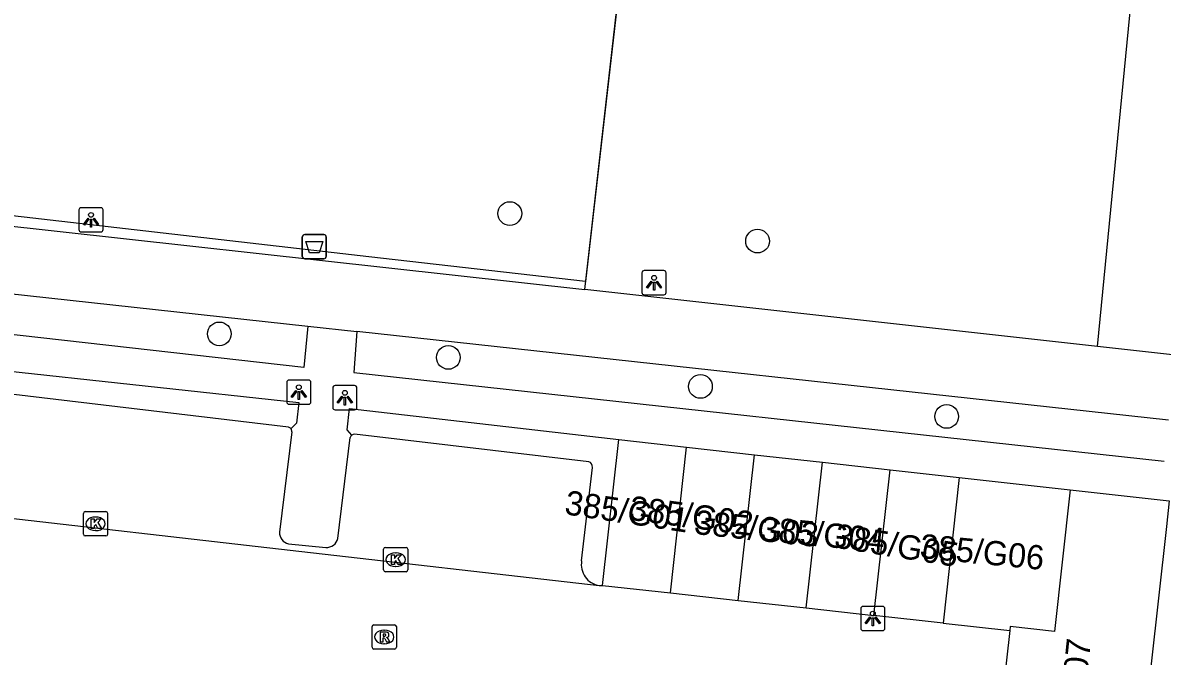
# Model space of a CAD drawing. Extents: x 162026 to 163499, y 387297 to 388169.
# Drawn here: x 162130.69 to 162177.68, y 387827.91 to 387854.05 of the extents above; entities that cross this region are included whole.
import ezdxf

# ---------------------------------------------------------------- set-up
doc = ezdxf.new("R2010")
doc.units = 0
for name, color, linetype in [('IMGEO_Afvalbak', 7, 'Continuous'), ('IMGEO_Boom', 7, 'Continuous'), ('IMGEO_Fietspad_gesloten', 7, 'Continuous'), ('IMGEO_Groenvoorziening', 7, 'Continuous'), ('IMGEO_Hek', 7, 'Continuous'), ('IMGEO_Kolk', 7, 'Continuous'), ('IMGEO_Lichtpunt', 7, 'Continuous'), ('IMGEO_Loofbos', 7, 'Continuous'), ('IMGEO_Pand', 7, 'Continuous'), ('IMGEO_Pand_nummerreeks', 7, 'Continuous'), ('IMGEO_Parkeervlak_open', 7, 'Continuous'), ('IMGEO_Rijbaan_lokaal_open', 7, 'Continuous'), ('IMGEO_Rioolput', 7, 'Continuous'), ('IMGEO_Voetpad_open', 7, 'Continuous')]:
    doc.layers.add(name, color=color, linetype=linetype)

msp = doc.modelspace()

# ---------------------------------------------------------------- linework, layer by layer
at = {"layer": 'IMGEO_Afvalbak'}
for p, q in [((162142.22, 387844.41), (162142.22, 387845.21)), ((162142.22, 387845.21), (162142.22, 387844.41)), ((162142.32, 387845.31), (162143.11, 387845.31)), ((162143.11, 387845.31), (162142.32, 387845.31)), ((162143.21, 387845.21), (162143.21, 387844.41)), ((162143.21, 387844.41), (162143.21, 387845.21)), ((162143.11, 387844.31), (162142.32, 387844.31)), ((162142.32, 387844.31), (162143.11, 387844.31))]:
    msp.add_line(p, q, dxfattribs=at)
msp.add_lwpolyline([(162142.363, 387845.024), (162143.067, 387845.024), (162142.918, 387844.554), (162142.512, 387844.554), (162142.363, 387845.024)], dxfattribs=at)
for centre, start, end in [((162142.32, 387845.21), 90, 180), ((162142.32, 387845.21), 90, 180), ((162143.11, 387845.21), 0, 90), ((162143.11, 387845.21), 360, 90), ((162142.32, 387844.41), 180, 270), ((162142.32, 387844.41), 180, 270), ((162143.11, 387844.41), 270, 0), ((162143.11, 387844.41), 270, 0)]:
    msp.add_arc(centre, 0.1, start, end, dxfattribs=at)
at = {"layer": 'IMGEO_Boom'}
for centre in [(162150.777, 387846.176), (162160.995, 387845.04), (162138.798, 387841.21), (162148.243, 387840.242), (162158.638, 387839.043), (162168.793, 387837.806)]:
    msp.add_circle(centre, 0.489, dxfattribs=at)
at = {"layer": 'IMGEO_Fietspad_gesloten'}
for points in [[(162124.015, 387846.348), (162153.864, 387843.037)], [(162123.707, 387843.579), (162142.441, 387841.533)], [(162175.011, 387840.691), (162153.864, 387843.037)], [(162142.441, 387841.533), (162144.47, 387841.312)], [(162177.938, 387837.659), (162144.47, 387841.312)], [(162179.708, 387840.17), (162175.011, 387840.691)]]:
    msp.add_lwpolyline(points, dxfattribs=at)
at = {"layer": 'IMGEO_Groenvoorziening'}
msp.add_lwpolyline([(162153.864, 387843.037), (162155.543, 387857.784), (162125.681, 387861.129)], dxfattribs=at)
at = {"layer": 'IMGEO_Hek'}
msp.add_lwpolyline([(162125.681, 387861.129), (162155.543, 387857.784), (162153.902, 387843.37), (162144.961, 387844.395), (162141.98, 387844.737), (162124.046, 387846.793)], dxfattribs=at)
at = {"layer": 'IMGEO_Kolk'}
for p, q in [((162133.192, 387832.952), (162133.192, 387833.804)), ((162133.267, 387833.878), (162134.119, 387833.878)), ((162134.193, 387833.804), (162134.193, 387832.952)), ((162133.68, 387833.658), (162133.705, 387833.658)), ((162134.119, 387832.878), (162133.267, 387832.878)), ((162133.703, 387833.098), (162133.678, 387833.098)), ((162145.646, 387832.401), (162146.498, 387832.401)), ((162145.571, 387831.475), (162145.571, 387832.327)), ((162146.059, 387832.181), (162146.084, 387832.181)), ((162146.572, 387832.327), (162146.572, 387831.475)), ((162146.082, 387831.621), (162146.057, 387831.621)), ((162146.498, 387831.401), (162145.646, 387831.401))]:
    msp.add_line(p, q, dxfattribs=at)
for points in [[(162133.192, 387832.952), (162133.192, 387833.804)], [(162133.267, 387833.878), (162134.119, 387833.878)], [(162134.193, 387833.804), (162134.193, 387832.952)], [(162133.513, 387833.578), (162133.636, 387833.578), (162133.636, 387833.427), (162133.766, 387833.578), (162133.93, 387833.578), (162133.784, 387833.427), (162133.937, 387833.178), (162133.785, 387833.178), (162133.7, 387833.342), (162133.636, 387833.275), (162133.636, 387833.178), (162133.513, 387833.178), (162133.513, 387833.578)], [(162134.119, 387832.878), (162133.267, 387832.878)], [(162145.646, 387832.401), (162146.498, 387832.401)], [(162145.571, 387831.475), (162145.571, 387832.327)], [(162145.892, 387832.101), (162146.015, 387832.101), (162146.015, 387831.95), (162146.145, 387832.101), (162146.309, 387832.101), (162146.163, 387831.95), (162146.316, 387831.701), (162146.164, 387831.701), (162146.079, 387831.865), (162146.015, 387831.798), (162146.015, 387831.701), (162145.892, 387831.701), (162145.892, 387832.101)], [(162146.572, 387832.327), (162146.572, 387831.475)], [(162146.498, 387831.401), (162145.646, 387831.401)]]:
    msp.add_lwpolyline(points, dxfattribs=at)
for centre, start, end in [((162133.269, 387833.802), 91.552, 178.448), ((162133.269, 387833.802), 91.552, 178.448), ((162134.117, 387833.802), 1.552, 88.448), ((162134.117, 387833.802), 1.552, 88.448), ((162133.269, 387832.954), 181.552, 268.448), ((162133.269, 387832.954), 181.552, 268.448), ((162134.117, 387832.954), 271.552, 358.448), ((162134.117, 387832.954), 271.552, 358.448), ((162145.648, 387832.325), 91.552, 178.448), ((162145.648, 387832.325), 91.552, 178.448), ((162146.496, 387832.325), 1.552, 88.448), ((162146.496, 387832.325), 1.552, 88.448), ((162145.648, 387831.477), 181.552, 268.448), ((162145.648, 387831.477), 181.552, 268.448), ((162146.496, 387831.477), 271.552, 358.448), ((162146.496, 387831.477), 271.552, 358.448)]:
    msp.add_arc(centre, 0.0765, start, end, dxfattribs=at)
for centre, major_axis, ratio, start_param, end_param in [((162133.679, 387833.378), (-0.387, 0.002), 0.722429, 4.712389, 7.853982), ((162133.704, 387833.378), (-0.39, 0.002), 0.717154, 1.570796, 4.712389), ((162146.058, 387831.901), (-0.387, 0.002), 0.722429, 4.712389, 7.853982), ((162146.083, 387831.901), (-0.39, 0.002), 0.717154, 1.570796, 4.712389)]:
    msp.add_ellipse(centre, major_axis=major_axis, ratio=ratio, start_param=start_param, end_param=end_param, dxfattribs=at)
at = {"layer": 'IMGEO_Lichtpunt'}
for p, q in [((162133.009, 387846.322), (162133.009, 387845.515)), ((162133.009, 387846.322), (162133.009, 387845.515)), ((162133.911, 387846.417), (162133.103, 387846.417)), ((162133.911, 387846.417), (162133.103, 387846.417)), ((162134.005, 387845.515), (162134.005, 387846.322)), ((162134.005, 387845.515), (162134.005, 387846.322)), ((162133.103, 387845.421), (162133.911, 387845.421)), ((162133.103, 387845.421), (162133.911, 387845.421)), ((162156.228, 387843.725), (162156.228, 387842.918)), ((162156.228, 387843.725), (162156.228, 387842.918)), ((162157.13, 387843.82), (162156.322, 387843.82)), ((162157.13, 387843.82), (162156.322, 387843.82)), ((162157.224, 387842.918), (162157.224, 387843.725)), ((162157.224, 387842.918), (162157.224, 387843.725)), ((162156.322, 387842.824), (162157.13, 387842.824)), ((162156.322, 387842.824), (162157.13, 387842.824)), ((162141.578, 387839.213), (162141.578, 387838.406)), ((162141.578, 387839.213), (162141.578, 387838.406)), ((162142.48, 387839.308), (162141.672, 387839.308)), ((162142.48, 387839.308), (162141.672, 387839.308)), ((162142.574, 387838.406), (162142.574, 387839.213)), ((162142.574, 387838.406), (162142.574, 387839.213)), ((162143.477, 387838.983), (162143.477, 387838.176)), ((162143.477, 387838.983), (162143.477, 387838.176)), ((162144.379, 387839.078), (162143.571, 387839.078)), ((162144.379, 387839.078), (162143.571, 387839.078)), ((162144.473, 387838.176), (162144.473, 387838.983)), ((162144.473, 387838.176), (162144.473, 387838.983)), ((162141.672, 387838.312), (162142.48, 387838.312)), ((162141.672, 387838.312), (162142.48, 387838.312)), ((162143.571, 387838.082), (162144.379, 387838.082)), ((162143.571, 387838.082), (162144.379, 387838.082)), ((162165.25, 387829.876), (162165.25, 387829.069)), ((162165.25, 387829.876), (162165.25, 387829.069)), ((162166.152, 387829.971), (162165.344, 387829.971)), ((162166.152, 387829.971), (162165.344, 387829.971)), ((162166.246, 387829.069), (162166.246, 387829.876)), ((162166.246, 387829.069), (162166.246, 387829.876)), ((162165.344, 387828.975), (162166.152, 387828.975)), ((162165.344, 387828.975), (162166.152, 387828.975))]:
    msp.add_line(p, q, dxfattribs=at)
for points in [[(162133.383, 387845.986), (162133.422, 387845.958), (162133.234, 387845.696), (162133.196, 387845.723), (162133.383, 387845.986)], [(162133.485, 387845.938), (162133.532, 387845.938), (162133.532, 387845.616), (162133.485, 387845.616), (162133.485, 387845.938)], [(162133.595, 387845.958), (162133.633, 387845.985), (162133.82, 387845.723), (162133.781, 387845.695), (162133.595, 387845.958)], [(162156.602, 387843.389), (162156.641, 387843.361), (162156.453, 387843.099), (162156.415, 387843.126), (162156.602, 387843.389)], [(162156.704, 387843.341), (162156.751, 387843.341), (162156.751, 387843.019), (162156.704, 387843.019), (162156.704, 387843.341)], [(162156.814, 387843.361), (162156.852, 387843.388), (162157.039, 387843.126), (162157, 387843.098), (162156.814, 387843.361)], [(162141.952, 387838.877), (162141.991, 387838.849), (162141.803, 387838.587), (162141.765, 387838.614), (162141.952, 387838.877)], [(162142.054, 387838.829), (162142.101, 387838.829), (162142.101, 387838.507), (162142.054, 387838.507), (162142.054, 387838.829)], [(162142.164, 387838.849), (162142.202, 387838.876), (162142.389, 387838.614), (162142.35, 387838.586), (162142.164, 387838.849)], [(162143.851, 387838.647), (162143.89, 387838.619), (162143.702, 387838.357), (162143.664, 387838.384), (162143.851, 387838.647)], [(162143.953, 387838.599), (162144, 387838.599), (162144, 387838.277), (162143.953, 387838.277), (162143.953, 387838.599)], [(162144.063, 387838.619), (162144.101, 387838.646), (162144.288, 387838.384), (162144.249, 387838.356), (162144.063, 387838.619)], [(162165.624, 387829.54), (162165.663, 387829.512), (162165.475, 387829.25), (162165.437, 387829.277), (162165.624, 387829.54)], [(162165.726, 387829.492), (162165.773, 387829.492), (162165.773, 387829.17), (162165.726, 387829.17), (162165.726, 387829.492)], [(162165.836, 387829.512), (162165.874, 387829.539), (162166.061, 387829.277), (162166.022, 387829.249), (162165.836, 387829.512)]]:
    msp.add_lwpolyline(points, dxfattribs=at)
for centre in [(162133.508, 387846.12), (162156.727, 387843.523), (162142.077, 387839.011), (162143.976, 387838.781), (162165.749, 387829.674)]:
    msp.add_circle(centre, 0.0994, dxfattribs=at)
for centre, start, end in [((162133.103, 387846.322), 90, 180), ((162133.103, 387846.322), 90, 180), ((162133.911, 387846.322), 0, 90), ((162133.911, 387846.322), 0, 90), ((162133.103, 387845.515), 180, 270), ((162133.103, 387845.515), 180, 270), ((162133.911, 387845.515), 270, 0), ((162133.911, 387845.515), 270, 360), ((162156.322, 387843.725), 90, 180), ((162156.322, 387843.725), 90, 180), ((162157.13, 387843.725), 0, 90), ((162157.13, 387843.725), 0, 90), ((162156.322, 387842.918), 180, 270), ((162156.322, 387842.918), 180, 270), ((162157.13, 387842.918), 270, 0), ((162157.13, 387842.918), 270, 360), ((162141.672, 387839.213), 90, 180), ((162141.672, 387839.213), 90, 180), ((162142.48, 387839.213), 0, 90), ((162142.48, 387839.213), 0, 90), ((162143.571, 387838.983), 90, 180), ((162143.571, 387838.983), 90, 180), ((162144.379, 387838.983), 0, 90), ((162144.379, 387838.983), 0, 90), ((162141.672, 387838.406), 180, 270), ((162141.672, 387838.406), 180, 270), ((162142.48, 387838.406), 270, 0), ((162142.48, 387838.406), 270, 360), ((162143.571, 387838.176), 180, 270), ((162143.571, 387838.176), 180, 270), ((162144.379, 387838.176), 270, 0), ((162144.379, 387838.176), 270, 360), ((162165.344, 387829.876), 90, 180), ((162165.344, 387829.876), 90, 180), ((162166.152, 387829.876), 0, 90), ((162166.152, 387829.876), 0, 90), ((162165.344, 387829.069), 180, 270), ((162165.344, 387829.069), 180, 270), ((162166.152, 387829.069), 270, 0), ((162166.152, 387829.069), 270, 360)]:
    msp.add_arc(centre, 0.0946, start, end, dxfattribs=at)
at = {"layer": 'IMGEO_Loofbos'}
msp.add_lwpolyline([(162175.011, 387840.691), (162177.571, 387866.907), (162177.598, 387868.402), (162177.312, 387869.89), (162176.723, 387871.285), (162175.856, 387872.528), (162167.785, 387879.745), (162165.386, 387881.891)], dxfattribs=at)
at = {"layer": 'IMGEO_Pand'}
for points in [[(162154.604, 387830.837), (162155.272, 387836.851)], [(162155.272, 387836.851), (162158.07, 387836.54)], [(162157.402, 387830.526), (162158.07, 387836.54)], [(162158.07, 387836.54), (162160.868, 387836.229)], [(162160.2, 387830.215), (162160.868, 387836.229)], [(162160.868, 387836.229), (162163.666, 387835.918)], [(162162.997, 387829.904), (162163.666, 387835.918)], [(162163.666, 387835.918), (162166.464, 387835.607)], [(162165.795, 387829.593), (162166.464, 387835.607)], [(162166.464, 387835.607), (162169.313, 387835.29)], [(162169.313, 387835.29), (162168.645, 387829.276)], [(162169.313, 387835.29), (162173.885, 387834.782)], [(162173.885, 387834.782), (162173.236, 387828.935), (162171.409, 387829.139), (162171.391, 387828.971)], [(162173.885, 387834.782), (162177.973, 387834.328)], [(162177.973, 387834.328), (162177.854, 387833.262), (162176.897, 387824.645)], [(162154.604, 387830.837), (162157.402, 387830.526)], [(162157.402, 387830.526), (162160.2, 387830.215)], [(162160.2, 387830.215), (162162.997, 387829.904)], [(162162.997, 387829.904), (162165.795, 387829.593)], [(162168.645, 387829.276), (162165.795, 387829.593)], [(162168.645, 387829.276), (162171.391, 387828.971)], [(162171.391, 387828.971), (162170.983, 387825.303)]]:
    msp.add_lwpolyline(points, dxfattribs=at)
at = {"layer": 'IMGEO_Parkeervlak_open'}
for points in [[(162141.646, 387837.364), (162129.498, 387838.809)], [(162154.033, 387835.938), (162144.372, 387837.077)], [(162153.739, 387831.847), (162154.185, 387835.704)]]:
    msp.add_lwpolyline(points, dxfattribs=at)
for centre, radius, start, end in [((162141.609, 387837.191), 0.177, 35.6723, 77.9418), ((162144.375, 387836.898), 0.179, 90.9975, 127.4863), ((162153.968, 387835.73), 0.218, 353.2879, 72.7254), ((162154.596, 387831.691), 0.871, 169.6626, 261.0817)]:
    msp.add_arc(centre, radius, start, end, dxfattribs=at)
at = {"layer": 'IMGEO_Rijbaan_lokaal_open'}
for points in [[(162128.746, 387833.776), (162141.717, 387832.294), (162154.461, 387830.83)], [(162154.461, 387830.83), (162154.604, 387830.837)]]:
    msp.add_lwpolyline(points, dxfattribs=at)
at = {"layer": 'IMGEO_Rioolput'}
for p, q in [((162145.098, 387828.283), (162145.098, 387829.135)), ((162145.173, 387829.209), (162146.025, 387829.209)), ((162146.099, 387829.135), (162146.099, 387828.283)), ((162145.586, 387828.989), (162145.611, 387828.989)), ((162146.025, 387828.209), (162145.173, 387828.209)), ((162145.609, 387828.429), (162145.584, 387828.429))]:
    msp.add_line(p, q, dxfattribs=at)
for points in [[(162145.098, 387828.283), (162145.098, 387829.135)], [(162145.173, 387829.209), (162146.025, 387829.209)], [(162146.099, 387829.135), (162146.099, 387828.283)], [(162145.687, 387828.907), (162145.435, 387828.909), (162145.435, 387828.509)], [(162145.435, 387828.509), (162145.559, 387828.509), (162145.559, 387828.671), (162145.57, 387828.671)], [(162145.613, 387828.828), (162145.559, 387828.828), (162145.559, 387828.747)], [(162145.559, 387828.747), (162145.611, 387828.747)], [(162145.617, 387828.642), (162145.688, 387828.509), (162145.828, 387828.509), (162145.763, 387828.635)], [(162146.025, 387828.209), (162145.173, 387828.209)]]:
    msp.add_lwpolyline(points, dxfattribs=at)
for centre, radius, start, end in [((162145.175, 387829.133), 0.0765, 91.552, 178.448), ((162145.175, 387829.133), 0.0765, 91.552, 178.448), ((162146.023, 387829.133), 0.0765, 1.552, 88.448), ((162146.023, 387829.133), 0.0765, 1.552, 88.448), ((162145.569, 387828.618), 0.0533, 26.0293, 88.6989), ((162145.595, 387828.936), 0.19, 274.7715, 282.9687), ((162145.619, 387828.732), 0.0964, 77.0061, 93.1865), ((162145.633, 387828.789), 0.0378, 276.6634, 79.6772), ((162145.686, 387828.797), 0.109, 350.3612, 89.416), ((162145.684, 387828.797), 0.112, 277.5842, 350.9817), ((162145.668, 387828.582), 0.108, 29.5134, 73.7905), ((162145.175, 387828.285), 0.0765, 181.552, 268.448), ((162145.175, 387828.285), 0.0765, 181.552, 268.448), ((162146.023, 387828.285), 0.0765, 271.552, 358.448), ((162146.023, 387828.285), 0.0765, 271.552, 358.448)]:
    msp.add_arc(centre, radius, start, end, dxfattribs=at)
for centre, major_axis, ratio, start_param, end_param in [((162145.585, 387828.709), (-0.387, 0.002), 0.722429, 4.712389, 7.853982), ((162145.61, 387828.709), (-0.39, 0.002), 0.717154, 1.570796, 4.712389)]:
    msp.add_ellipse(centre, major_axis=major_axis, ratio=ratio, start_param=start_param, end_param=end_param, dxfattribs=at)
at = {"layer": 'IMGEO_Voetpad_open'}
for points in [[(162142.441, 387841.533), (162142.287, 387839.823), (162124.231, 387841.861), (162123.536, 387841.932)], [(162144.47, 387841.312), (162144.349, 387839.619), (162177.764, 387835.959)], [(162129.386, 387839.759), (162142.079, 387838.375), (162141.978, 387837.533), (162141.753, 387837.294)], [(162144.266, 387837.04), (162144.066, 387837.252), (162144.169, 387838.128), (162155.272, 387836.851)], [(162141.785, 387837.175), (162141.282, 387833.03)], [(162143.691, 387832.771), (162144.199, 387836.937)], [(162141.656, 387832.557), (162143.192, 387832.402)]]:
    msp.add_lwpolyline(points, dxfattribs=at)
for centre, radius, start, end in [((162141.612, 387837.192), 0.174, 354.3157, 35.7867), ((162144.385, 387836.89), 0.191, 128.2412, 165.6719), ((162141.745, 387833.012), 0.464, 177.7595, 258.9072), ((162143.22, 387832.886), 0.484, 266.6509, 346.3134)]:
    msp.add_arc(centre, radius, start, end, dxfattribs=at)

# ---------------------------------------------------------------- texts
at = {"layer": 'IMGEO_Pand_nummerreeks'}
for s, rotation, p in [('385/G01', 351.4164, (162152.998, 387833.778)), ('385/G02', 352.4762, (162155.661, 387833.55)), ('385/G03', 353.8845, (162158.349, 387832.963)), ('385/G04', 354.4007, (162161.076, 387832.694)), ('385/G05', 350.8698, (162164.118, 387832.407)), ('385/G06', 354.3595, (162167.655, 387831.974)), ('385/G07', 84.1226, (162174.224, 387823.485))]:
    msp.add_text(s, height=1, rotation=rotation, dxfattribs=at).set_placement(p)

doc.saveas('drawing.dxf')
